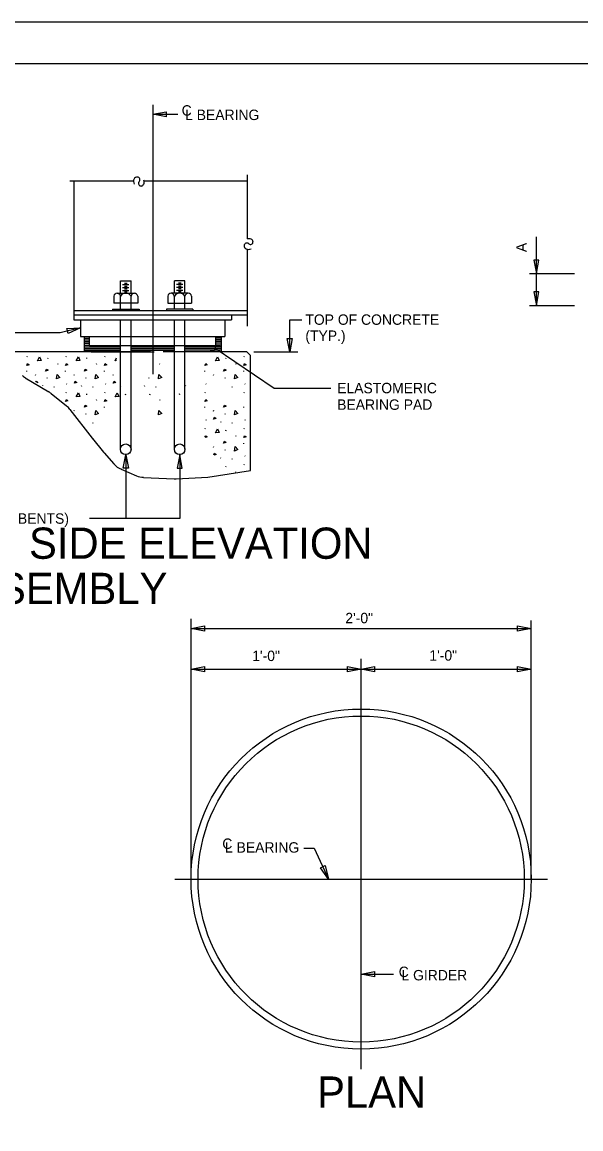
# Model space of a CAD drawing. Extents: x -125.5 to -89.4, y -5.1 to 16.9.
# Drawn here: x -112.46 to -105.75, y 3.64 to 16.93 of the extents above; entities that cross this region are included whole.
import ezdxf

# ---------------------------------------------------------------- set-up
doc = ezdxf.new("R2010")
doc.units = 0
for name, color, linetype in [('BR_AUTO DIMENSION', 7, 'Continuous'), ('BR_BORDER LINES', 7, 'Continuous'), ('BR_CENTER LINES', 7, 'Continuous'), ('BR_CONCRETE', 7, 'Continuous'), ('BR_REBAR', 7, 'Continuous'), ('BR_STRUCTURAL STEEL', 7, 'Continuous'), ('BR_TEXT', 7, 'Continuous'), ('Default', 7, 'Continuous'), ('Level 31', 7, 'Continuous')]:
    doc.layers.add(name, color=color, linetype=linetype)

msp = doc.modelspace()

# ---------------------------------------------------------------- linework, layer by layer
at = {"layer": 'BR_AUTO DIMENSION'}
for p, q in [((-110.889, 15.827), (-110.588, 15.827)), ((-106.282, 13.53), (-106.282, 14.357)), ((-106.365, 13.914), (-105.826, 13.914)), ((-106.365, 13.53), (-105.826, 13.53)), ((-109.244, 12.973), (-109.244, 13.36)), ((-109.244, 13.36), (-109.1, 13.36)), ((-112.001, 13.204), (-112.841, 13.204)), ((-111.755, 13.264), (-112.001, 13.204)), ((-110.139, 13.018), (-109.432, 12.538)), ((-109.674, 12.973), (-109.147, 12.973)), ((-109.432, 12.538), (-108.749, 12.538)), ((-111.213, 11.74), (-111.213, 10.973)), ((-110.565, 11.74), (-110.565, 10.973)), ((-110.565, 10.973), (-111.648, 10.973)), ((-110.428, 7.085), (-110.428, 9.766)), ((-106.344, 7.085), (-106.344, 9.749)), ((-110.428, 9.653), (-106.344, 9.653)), ((-110.428, 9.163), (-106.344, 9.163)), ((-110.428, 6.643), (-110.428, 8.478)), ((-106.344, 6.643), (-106.344, 8.478)), ((-109.075, 7.015), (-108.949, 7.015)), ((-108.949, 7.015), (-108.78, 6.643)), ((-108.386, 5.501), (-107.996, 5.501))]:
    msp.add_line(p, q, dxfattribs=at)
for points in [[(-110.726, 15.796), (-110.889, 15.827), (-110.726, 15.858)], [(-106.314, 14.077), (-106.282, 13.914), (-106.251, 14.077)], [(-106.314, 13.693), (-106.282, 13.53), (-106.251, 13.693)], [(-111.919, 13.256), (-111.754, 13.264), (-111.905, 13.195)], [(-109.213, 13.135), (-109.244, 12.973), (-109.275, 13.135)], [(-111.244, 11.577), (-111.213, 11.739), (-111.181, 11.577)], [(-110.534, 11.577), (-110.565, 11.739), (-110.596, 11.577)], [(-110.265, 9.621), (-110.428, 9.653), (-110.265, 9.684)], [(-106.507, 9.684), (-106.344, 9.653), (-106.507, 9.621)], [(-110.265, 9.132), (-110.428, 9.163), (-110.265, 9.194)], [(-108.549, 9.194), (-108.386, 9.163), (-108.549, 9.132)], [(-108.224, 9.132), (-108.386, 9.163), (-108.224, 9.194)], [(-106.507, 9.194), (-106.344, 9.163), (-106.507, 9.132)], [(-108.819, 6.804), (-108.78, 6.643), (-108.876, 6.778)], [(-108.224, 5.47), (-108.386, 5.501), (-108.224, 5.532)]]:
    msp.add_lwpolyline(points, close=True, dxfattribs=at)
for centre, start, end in [((-110.103, 13.015), 53.0627, 175.5269), ((-110.176, 13.021), 233.0627, 355.5269)]:
    msp.add_arc(centre, 0.0366, start, end, dxfattribs=at)
at = {"layer": 'BR_BORDER LINES'}
msp.add_line((-90.033, 16.434), (-123.699, 16.434), dxfattribs=at)
at = {"layer": 'BR_CENTER LINES'}
for p, q in [((-110.889, 15.941), (-110.889, 12.708)), ((-108.386, 4.359), (-108.386, 9.288)), ((-110.622, 6.643), (-106.147, 6.643))]:
    msp.add_line(p, q, dxfattribs=at)
at = {"layer": 'BR_CONCRETE'}
for p, q in [((-110.915, 12.973), (-112.775, 12.973)), ((-111.629, 12.973), (-110.871, 12.973)), ((-109.758, 12.973), (-110.762, 12.973)), ((-109.758, 12.973), (-109.716, 12.931)), ((-109.716, 11.551), (-109.716, 12.931))]:
    msp.add_line(p, q, dxfattribs=at)
at = {"layer": 'BR_REBAR'}
for p, q in [((-111.276, 13.827), (-111.149, 13.827)), ((-111.276, 13.678), (-111.276, 13.827)), ((-111.149, 13.678), (-111.149, 13.827)), ((-110.502, 13.827), (-110.629, 13.827)), ((-110.629, 13.678), (-110.629, 13.827)), ((-110.502, 13.678), (-110.502, 13.827)), ((-111.251, 13.782), (-111.174, 13.782)), ((-111.251, 13.748), (-111.174, 13.748)), ((-111.251, 13.713), (-111.174, 13.713)), ((-111.229, 13.8), (-111.197, 13.8)), ((-111.229, 13.765), (-111.197, 13.765)), ((-111.229, 13.73), (-111.197, 13.73)), ((-111.229, 13.696), (-111.197, 13.696)), ((-110.527, 13.782), (-110.603, 13.782)), ((-110.527, 13.748), (-110.603, 13.748)), ((-110.527, 13.713), (-110.603, 13.713)), ((-110.549, 13.8), (-110.581, 13.8)), ((-110.549, 13.765), (-110.581, 13.765)), ((-110.549, 13.73), (-110.581, 13.73)), ((-110.549, 13.696), (-110.581, 13.696)), ((-111.356, 13.644), (-111.356, 13.557)), ((-111.069, 13.557), (-111.356, 13.557)), ((-111.316, 13.678), (-111.109, 13.678)), ((-111.276, 13.488), (-111.276, 13.644)), ((-111.149, 13.488), (-111.149, 13.644)), ((-111.069, 13.644), (-111.069, 13.557)), ((-110.709, 13.644), (-110.709, 13.557)), ((-110.709, 13.557), (-110.422, 13.557)), ((-110.462, 13.678), (-110.669, 13.678)), ((-110.629, 13.488), (-110.629, 13.644)), ((-110.502, 13.488), (-110.502, 13.644)), ((-110.422, 13.644), (-110.422, 13.557)), ((-111.372, 13.488), (-111.372, 13.47)), ((-111.372, 13.488), (-111.053, 13.488)), ((-111.053, 13.488), (-111.053, 13.47)), ((-110.724, 13.488), (-110.724, 13.47)), ((-110.406, 13.488), (-110.724, 13.488)), ((-110.406, 13.488), (-110.406, 13.47)), ((-111.276, 13.15), (-111.276, 13.358)), ((-111.149, 13.15), (-111.149, 13.358)), ((-110.629, 13.15), (-110.629, 13.358)), ((-110.502, 13.15), (-110.502, 13.358)), ((-111.276, 12.962), (-111.276, 13.16)), ((-111.149, 12.962), (-111.149, 13.16)), ((-110.629, 12.962), (-110.629, 13.16)), ((-110.502, 12.962), (-110.502, 13.16)), ((-111.276, 11.804), (-111.276, 12.962)), ((-111.149, 11.804), (-111.149, 12.962)), ((-110.629, 11.804), (-110.629, 12.962)), ((-110.502, 11.804), (-110.502, 12.962))]:
    msp.add_line(p, q, dxfattribs=at)
for centre in [(-111.213, 11.804), (-110.565, 11.804)]:
    msp.add_circle(centre, 0.0637, dxfattribs=at)
for centre, major_axis, start_param, end_param in [((-111.316, 13.634), (0, 0.0444), 4.933703, 7.632667), ((-111.213, 13.592), (0, 0.0867), 5.35589, 7.210481), ((-111.109, 13.634), (0, 0.0444), 4.933703, 7.632667), ((-110.669, 13.634), (0, 0.0444), 4.933703, 7.632667), ((-110.565, 13.592), (0, 0.0867), 5.35589, 7.210481), ((-110.462, 13.634), (0, 0.0444), 4.933703, 7.632667)]:
    msp.add_ellipse(centre, major_axis=major_axis, ratio=0.918783, start_param=start_param, end_param=end_param, dxfattribs=at)
at = {"layer": 'BR_STRUCTURAL STEEL'}
for p, q in [((-111.837, 15.028), (-111.837, 13.42)), ((-111.837, 13.47), (-109.75, 13.47)), ((-111.837, 13.42), (-110.588, 13.42)), ((-111.837, 13.42), (-111.837, 13.358)), ((-111.837, 13.358), (-109.941, 13.358)), ((-111.754, 13.358), (-111.754, 13.16)), ((-111.372, 13.358), (-111.053, 13.358)), ((-110.588, 13.42), (-109.75, 13.42)), ((-110.024, 13.358), (-110.024, 13.16)), ((-109.941, 13.42), (-109.941, 13.358)), ((-111.754, 13.16), (-110.024, 13.16)), ((-111.713, 13.16), (-111.713, 12.973)), ((-111.648, 13.049), (-111.648, 13.16)), ((-110.13, 13.049), (-110.13, 13.16)), ((-110.065, 13.16), (-110.065, 12.973)), ((-111.648, 13.049), (-110.13, 13.049))]:
    msp.add_line(p, q, dxfattribs=at)
for radius in [2.042, 1.958]:
    msp.add_circle((-108.386, 6.643), radius, dxfattribs=at)
at = {"layer": 'BR_TEXT'}
for p, q in [((-111.885, 15.028), (-111.119, 15.028)), ((-110.993, 15.028), (-109.75, 15.028)), ((-109.75, 14.331), (-109.75, 15.099)), ((-109.75, 13.282), (-109.75, 14.205))]:
    msp.add_line(p, q, dxfattribs=at)
for centre, radius, start, end in [((-111.049, 15.021), 0.0705, 155.6187, 208.3414), ((-111.077, 15.034), 0.0399, 83.2422, 155.6187), ((-111.076, 15.04), 0.0334, 316.8236, 83.2422), ((-111.061, 15.016), 0.07, 335.6333, 17.6449), ((-111.03, 14.996), 0.0304, 136.8236, 275.5224), ((-111.03, 15.002), 0.0358, 275.5224, 335.6333), ((-109.758, 14.248), 0.0334, 46.8235, 173.2422), ((-109.752, 14.247), 0.0399, 173.2422, 245.6187), ((-109.734, 14.262), 0.07, 65.6333, 107.6449), ((-109.715, 14.294), 0.0304, 226.8236, 5.5224), ((-109.72, 14.294), 0.0358, 5.5224, 65.6333), ((-109.739, 14.275), 0.0705, 245.6187, 298.3414)]:
    msp.add_arc(centre, radius, start, end, dxfattribs=at)
at = {"layer": 'Default'}
for p, q in [((-111.713, 13.139), (-111.648, 13.139)), ((-111.713, 13.118), (-111.648, 13.118)), ((-111.713, 13.097), (-111.648, 13.097)), ((-111.713, 13.077), (-111.648, 13.077)), ((-111.713, 13.056), (-111.648, 13.056)), ((-111.713, 13.035), (-111.276, 13.035)), ((-111.149, 13.035), (-110.629, 13.035)), ((-110.065, 13.035), (-110.502, 13.035)), ((-110.065, 13.139), (-110.13, 13.139)), ((-110.065, 13.118), (-110.13, 13.118)), ((-110.065, 13.097), (-110.13, 13.097)), ((-110.065, 13.077), (-110.13, 13.077)), ((-110.065, 13.056), (-110.13, 13.056)), ((-112.396, 12.914), (-112.392, 12.923)), ((-112.148, 12.893), (-112.144, 12.901)), ((-111.929, 12.914), (-111.925, 12.923)), ((-111.713, 13.014), (-111.276, 13.014)), ((-111.713, 12.993), (-111.276, 12.993)), ((-111.681, 12.893), (-111.678, 12.901)), ((-111.462, 12.914), (-111.459, 12.923)), ((-111.149, 13.014), (-110.629, 13.014)), ((-111.149, 12.993), (-110.629, 12.993)), ((-110.065, 13.014), (-110.502, 13.014)), ((-110.065, 12.993), (-110.502, 12.993)), ((-110.009, 12.893), (-110.005, 12.901)), ((-109.79, 12.914), (-109.786, 12.923)), ((-112.032, 12.834), (-112.029, 12.828)), ((-111.566, 12.834), (-111.562, 12.828)), ((-110.806, 12.829), (-110.805, 12.828)), ((-109.893, 12.834), (-109.89, 12.828)), ((-112.42, 12.664), (-112.137, 12.495)), ((-112.406, 12.745), (-112.405, 12.737)), ((-112.298, 12.696), (-112.294, 12.704)), ((-112.157, 12.658), (-112.154, 12.666)), ((-111.939, 12.745), (-111.938, 12.737)), ((-111.831, 12.696), (-111.828, 12.704)), ((-111.691, 12.658), (-111.687, 12.666)), ((-111.472, 12.745), (-111.471, 12.737)), ((-111.365, 12.696), (-111.361, 12.704)), ((-110.934, 12.658), (-110.93, 12.666)), ((-110.267, 12.745), (-110.266, 12.737)), ((-110.159, 12.696), (-110.155, 12.704)), ((-110.018, 12.658), (-110.015, 12.666)), ((-109.8, 12.745), (-109.799, 12.737)), ((-112.214, 12.569), (-112.212, 12.566)), ((-112.073, 12.551), (-112.069, 12.559)), ((-111.922, 12.592), (-111.918, 12.587)), ((-111.747, 12.569), (-111.744, 12.563)), ((-111.607, 12.551), (-111.603, 12.559)), ((-111.455, 12.592), (-111.451, 12.587)), ((-111.281, 12.569), (-111.277, 12.563)), ((-110.991, 12.569), (-110.987, 12.563)), ((-110.85, 12.551), (-110.846, 12.559)), ((-110.497, 12.569), (-110.501, 12.563)), ((-110.25, 12.592), (-110.246, 12.587)), ((-109.934, 12.551), (-109.93, 12.559)), ((-109.783, 12.592), (-109.779, 12.587)), ((-112.108, 12.475), (-111.923, 12.324)), ((-111.929, 12.482), (-111.925, 12.49)), ((-111.681, 12.46), (-111.678, 12.469)), ((-111.566, 12.401), (-111.562, 12.395)), ((-111.462, 12.482), (-111.459, 12.49)), ((-111.215, 12.46), (-111.211, 12.469)), ((-110.925, 12.46), (-110.921, 12.469)), ((-110.809, 12.401), (-110.805, 12.395)), ((-110.563, 12.46), (-110.567, 12.469)), ((-110.257, 12.482), (-110.253, 12.49)), ((-109.79, 12.482), (-109.786, 12.49)), ((-111.882, 12.283), (-111.616, 11.938)), ((-111.831, 12.264), (-111.828, 12.272)), ((-111.691, 12.225), (-111.687, 12.234)), ((-111.472, 12.312), (-111.471, 12.304)), ((-110.267, 12.312), (-110.266, 12.304)), ((-110.159, 12.263), (-110.155, 12.272)), ((-110.018, 12.225), (-110.015, 12.234)), ((-109.8, 12.312), (-109.799, 12.304)), ((-111.607, 12.118), (-111.603, 12.126)), ((-110.25, 12.16), (-110.246, 12.154)), ((-110.075, 12.136), (-110.071, 12.131)), ((-109.934, 12.118), (-109.93, 12.126)), ((-109.783, 12.16), (-109.779, 12.154)), ((-110.257, 12.049), (-110.253, 12.057)), ((-110.009, 12.027), (-110.005, 12.036)), ((-109.893, 11.968), (-109.89, 11.963)), ((-109.79, 12.049), (-109.786, 12.057)), ((-111.612, 11.933), (-111.48, 11.77)), ((-110.159, 11.83), (-110.155, 11.839)), ((-109.8, 11.879), (-109.799, 11.871)), ((-111.473, 11.762), (-111.356, 11.629)), ((-110.075, 11.703), (-110.071, 11.698)), ((-110.018, 11.792), (-110.015, 11.801)), ((-109.783, 11.727), (-109.779, 11.721)), ((-111.266, 11.564), (-111.084, 11.487)), ((-110.009, 11.595), (-110.005, 11.603)), ((-109.934, 11.685), (-109.93, 11.693)), ((-109.79, 11.616), (-109.786, 11.624)), ((-110.999, 11.467), (-110.633, 11.449)), ((-109.893, 11.535), (-109.89, 11.53))]:
    msp.add_line(p, q, dxfattribs=at)
for points in [[(-112.273, 12.868), (-112.248, 12.915), (-112.229, 12.872), (-112.272, 12.868)], [(-111.806, 12.868), (-111.781, 12.915), (-111.762, 12.872), (-111.805, 12.868)], [(-111.34, 12.868), (-111.322, 12.901)], [(-110.134, 12.868), (-110.109, 12.915), (-110.09, 12.872), (-110.133, 12.868)], [(-112.402, 12.81), (-112.391, 12.833), (-112.372, 12.819), (-112.402, 12.81)], [(-112.176, 12.744), (-112.165, 12.767), (-112.146, 12.753), (-112.176, 12.744)], [(-111.935, 12.81), (-111.924, 12.833), (-111.906, 12.819), (-111.935, 12.81)], [(-111.709, 12.744), (-111.698, 12.767), (-111.679, 12.753), (-111.709, 12.744)], [(-111.469, 12.81), (-111.458, 12.833), (-111.439, 12.819), (-111.469, 12.81)], [(-111.324, 12.869), (-111.339, 12.868)], [(-110.263, 12.81), (-110.252, 12.833), (-110.233, 12.819), (-110.263, 12.81)], [(-110.037, 12.744), (-110.026, 12.767), (-110.007, 12.753), (-110.037, 12.744)], [(-109.796, 12.81), (-109.785, 12.833), (-109.767, 12.819), (-109.796, 12.81)], [(-112.045, 12.649), (-112.037, 12.701), (-112.004, 12.667), (-112.044, 12.649)], [(-111.578, 12.649), (-111.571, 12.701), (-111.538, 12.667), (-111.577, 12.649)], [(-110.821, 12.649), (-110.814, 12.701), (-110.781, 12.667), (-110.821, 12.649)], [(-109.906, 12.649), (-109.898, 12.701), (-109.865, 12.667), (-109.905, 12.649)], [(-112.291, 12.609), (-112.285, 12.622), (-112.267, 12.608), (-112.281, 12.604)], [(-111.829, 12.599), (-111.818, 12.622), (-111.8, 12.608), (-111.829, 12.599)], [(-111.363, 12.599), (-111.352, 12.622), (-111.333, 12.608), (-111.363, 12.599)], [(-111.935, 12.377), (-111.924, 12.4), (-111.906, 12.386), (-111.935, 12.377)], [(-111.806, 12.435), (-111.781, 12.482), (-111.762, 12.439), (-111.805, 12.435)], [(-111.469, 12.377), (-111.458, 12.4), (-111.439, 12.386), (-111.469, 12.377)], [(-111.34, 12.435), (-111.315, 12.482), (-111.295, 12.439), (-111.339, 12.435)], [(-110.263, 12.377), (-110.252, 12.4), (-110.233, 12.386), (-110.263, 12.377)], [(-111.709, 12.311), (-111.698, 12.334), (-111.679, 12.32), (-111.709, 12.311)], [(-111.578, 12.216), (-111.571, 12.269), (-111.538, 12.234), (-111.577, 12.216)], [(-110.821, 12.216), (-110.814, 12.269), (-110.781, 12.234), (-110.821, 12.216)], [(-110.037, 12.311), (-110.026, 12.334), (-110.007, 12.32), (-110.037, 12.311)], [(-109.906, 12.216), (-109.898, 12.269), (-109.865, 12.234), (-109.905, 12.216)], [(-110.157, 12.166), (-110.146, 12.189), (-110.127, 12.175), (-110.157, 12.166)], [(-110.261, 11.948), (-110.252, 11.967), (-110.233, 11.953), (-110.26, 11.945)], [(-110.134, 12.002), (-110.109, 12.05), (-110.09, 12.006), (-110.133, 12.002)], [(-109.796, 11.944), (-109.785, 11.967), (-109.767, 11.953), (-109.796, 11.944)], [(-110.037, 11.878), (-110.026, 11.901), (-110.007, 11.887), (-110.037, 11.878)], [(-109.906, 11.783), (-109.898, 11.836), (-109.865, 11.802), (-109.905, 11.783)], [(-110.156, 11.736), (-110.146, 11.756), (-110.127, 11.742), (-110.155, 11.734)], [(-110.607, 11.449), (-110.228, 11.47), (-109.716, 11.551)]]:
    msp.add_lwpolyline(points, dxfattribs=at)
for centre, start, end in [((-112.291, 12.879), 228.5648, 239.026), ((-112.266, 12.28), 50.9977, 59.026), ((-112.08, 12.13), 37.6364, 50.9977), ((-111.418, 12.09), 217.6364, 219.0825), ((-111.286, 11.928), 219.0825, 221.4122), ((-111.168, 11.794), 221.4122, 247.0596), ((-110.986, 11.717), 247.0596, 267.1364), ((-110.62, 11.699), 267.1364, 273.0953)]:
    msp.add_arc(centre, 0.25, start, end, dxfattribs=at)
at = {"layer": 'Level 31'}
msp.add_lwpolyline([(-125.533, -5.066), (-89.533, -5.066), (-89.533, 16.934), (-125.533, 16.934)], close=True, dxfattribs=at)

# ---------------------------------------------------------------- texts
at = {"layer": 'BR_AUTO DIMENSION'}
for s, p in [('C', (-110.541, 15.811)), ('L BEARING', (-110.5, 15.758)), ('TOP OF CONCRETE', (-109.056, 13.299)), ('(TYP.)', (-109.056, 13.106)), ('ELASTOMERIC', (-108.674, 12.477)), ('BEARING PAD', (-108.674, 12.278)), ('1 3/4"   ANCHOR BOLT (ALL BENTS)', (-114.731, 10.91))]:
    msp.add_text(s, height=0.125, dxfattribs=at).set_placement(p)
at = {"layer": 'BR_TEXT'}
for s, rotation, p in [('A', 90, (-106.399, 14.172)), ('C', 360, (-110.053, 7.005)), ('L BEARING', 360, (-110.021, 6.96))]:
    msp.add_text(s, height=0.125, rotation=rotation, dxfattribs=at).set_placement(p)
for s, height, p in [('SIDE ELEVATION', 0.375, (-112.374, 10.489)), ('BEARING ASSEMBLY', 0.375, (-115.812, 9.946)), ('2\'-0"', 0.125, (-108.576, 9.715)), ('1\'-0"', 0.125, (-109.694, 9.261)), ('1\'-0"', 0.125, (-107.567, 9.266)), ('C', 0.125, (-107.935, 5.466)), ('L GIRDER', 0.125, (-107.902, 5.426)), ('PLAN', 0.375, (-108.915, 3.897))]:
    msp.add_text(s, height=height, dxfattribs=at).set_placement(p)

doc.saveas('drawing.dxf')
